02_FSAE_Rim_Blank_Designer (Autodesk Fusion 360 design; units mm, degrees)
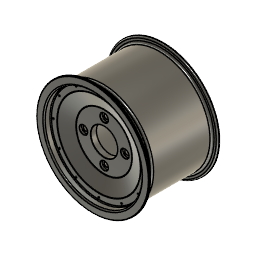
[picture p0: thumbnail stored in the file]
part number: 2026-07-27-09-56-27-671
sketch "Sketch1" plane through (0, 0, 0) normal (1, 0, 0) x axis (0, 1, 0)
  line L1 (153.5, 0) -> (0, 0)
  line L2 (0, 119.5) -> (0, 104)
  line L3 (143.5, 124.5) -> (5, 124.5)
  line L4 (148.5, 134.75) -> (148.5, 129.5)
  line L5 (153.5, 138.25) -> (152, 138.25)
  line L6 (2.5, 119.5) -> (2.5, 104)
  line L7 (143.5, 122) -> (5, 122)
  line L8 (151, 134.75) -> (151, 129.5)
  line L9 (153.5, 135.75) -> (152, 135.75)
  line L10 (2.5, 104) -> (0, 104)
  line L11 (153.5, 135.75) -> (153.5, 138.25)
  arc A1 centre (152, 134.75) radius 3.5 clockwise from (148.5, 134.75) to (152, 138.25)
  arc A2 centre (143.5, 129.5) radius 5 clockwise from (148.5, 129.5) to (143.5, 124.5)
  arc A3 centre (5, 119.5) radius 5 clockwise from (0, 119.5) to (5, 124.5)
  arc A4 centre (5, 119.5) radius 2.5 clockwise from (2.5, 119.5) to (5, 122)
  arc A5 centre (143.5, 129.5) radius 7.5 clockwise from (151, 129.5) to (143.5, 122)
  arc A6 centre (152, 134.75) radius 1 clockwise from (151, 134.75) to (152, 135.75)
  point P1 (0, 0)
  point P2 (0, 0)
  point P4 (0, 104)
  point P3 (153.5, 0)
  point P7 (153.5, 138.25)
  point P6 (148.5, 124.5)
  point P5 (0, 124.5)
  coincident P1 P2
  horizontal L1
  perpendicular L1 L2
  perpendicular L2 L3
  perpendicular L3 L4
  perpendicular L4 L5
  vertical P1 P4
  vertical P3 P7
  tangent L4 A1
  tangent L5 A1
  coincident P6 L3
  coincident P6 L4
  tangent L3 A2
  tangent L4 A2
  coincident P5 L2
  coincident P5 L3
  tangent L2 A3
  tangent L3 A3
  equal A2 A3
  perpendicular L6 L10
  perpendicular L9 L11
  dimension "d1" distance P2 P3 = 153.5
  dimension "d2" = 208
  dimension "d3" = 249
  dimension "d4" = 276.5
  dimension "d5" distance P5 P6 = 148.5
  dimension "d6" radius A1 = 3.5
  dimension "d7" radius A2 = 5
  dimension "d8" = 2.5
revolve "Revolve1" sketch "Sketch1" AlongAngle 360 bodies "FSAE Rim Back"
sketch "Sketch2" plane through (0, 0, 0) normal (0, -1, 0) x axis (1, 0, 0)
  circle C1 centre (0, 0) radius 104
  circle C2 centre (0, 0) radius 119.5
  circle C3 centre (0, 0) radius 112
  circle C4 centre (0, 112) radius 2.15
  point P1 (0, 0)
  point P3 (0, 0)
  point P4 (0, 112)
  coincident P1 P3
  coincident C3 P4
  vertical P3 P4
  dimension "d10" diameter C3 = 224
  dimension "d11" diameter C4 = 4.3
extrude "Extrude1" cut sketch "Sketch2" profile of C4 to an object
circular_pattern "C-Pattern1" TotalAngle 360
canvas "Canvas1"
move "Move1"
sketch "Sketch4" plane through (0, 0, 0) normal (1, 0, 0) x axis (0, 1, 0)
  line L1 (14, 0) -> (0, 0)
  line L2 (14, 72.5) -> (14, 0)
  line L3 (-8, 102.5) -> (14, 72.5)
  line L4 (-8, 124.5) -> (-8, 102.5)
  line L5 (-23.5, 124.5) -> (-8, 124.5)
  line L6 (-23.5, 138) -> (-23.5, 124.5)
  line L7 (-28.25, 138) -> (-23.5, 138)
  line L8 (-28.25, 0) -> (-28.25, 138)
  line L9 (0, 0) -> (-28.25, 0)
  line L10 (-13, 118.1658) -> (-28.25, 119.5)
  line L11 (-13, 102.5) -> (-13, 118.1658)
  line L12 (0, 68.6338) -> (-13, 102.5)
  line L13 (0, 0) -> (0, 68.6338)
  point P1 (0, 0)
  point P2 (0, 0)
  point P11 (0, 0)
  point P12 (-28.25, 119.5)
  point P5 (-8, 102.5)
  point P14 (-13, 102.5)
  point P3 (14, 0)
  point P4 (14, 72.5)
  point P6 (-8, 124.5)
  point P8 (-23.5, 138)
  point P9 (-28.25, 138)
  coincident P1 P2
  horizontal L1
  perpendicular L1 L2
  perpendicular L1 L4
  perpendicular L4 L5
  perpendicular L5 L6
  perpendicular L6 L7
  coincident P1 P11
  collinear L1 L9
  perpendicular L8 L9
  coincident L8 P12
  parallel L8 L11
  vertical L13
  horizontal P5 P14
  dimension "d29" distance P2 P3 = 14
  dimension "d30" = 145
  dimension "d31" = 205
  dimension "d32" = 249
  dimension "d33" = 276
  dimension "d34" distance P4 P6 = 22
  dimension "d35" distance P6 P8 = 15.5
  dimension "d36" distance P8 P9 = 4.75
  dimension "d37" distance L4 L11 = 5
  dimension "d38" angle L12 L13 = 159
  dimension "d39" angle L10 L11 = 95
  dimension "d40" = 239
revolve "Revolve3" sketch "Sketch4" AlongAngle 360 bodies "FSAE Rim Front"
sketch "Sketch5" plane through (0, 0, 0) normal (0, -1, 0) x axis (1, 0, 0)
  circle C1 centre (0, 0) radius 68.6338
  circle C2 centre (0, 0) radius 33
  point P1 (0, 0)
  point P3 (0, 0)
  coincident P1 P3
  dimension "d42" diameter C2 = 66
extrude "Extrude2" cut sketch "Sketch5" profile of C2 to an object
sketch "Sketch6" plane through (0, 0, 0) normal (0, -1, 0) x axis (1, 0, 0)
  circle C1 centre (0, 0) radius 33
  circle C2 centre (0, 0) radius 68.6338
  circle C3 centre (0, 0) radius 50.8
  point P1 (0, 0)
  point P4 (0, 0)
  point P3 (0, 50.8)
  coincident P1 P4
  coincident P3 C3
  vertical P1 P3
  dimension "d45" diameter C3 = 101.6
hole "Hole1" HoleDiameter 10.5 TipAngle 180 CBDepth 5 CBDiameter 20
chamfer "Chamfer2" sketch "Sketch1" distance 0.5
circular_pattern "C-Pattern2" TotalAngle 360
sketch "Sketch7" plane through (0, -13, 0) normal (0, -1, 0) x axis (1, 0, 0)
  circle C1 centre (0, 0) radius 102.5
  circle C2 centre (0, 0) radius 118.1658
  circle C3 centre (0, 0) radius 112
  point P1 (0, 0)
  point P3 (0, 0)
  point P4 (0, 112)
  coincident P1 P3
  coincident C3 P4
  vertical P1 P4
  dimension "d53" diameter C3 = 224
hole "Hole2" HoleDiameter 4.3 TipAngle 180
circular_pattern "C-Pattern3" TotalAngle 360
fillet "Fillet1" radius 1 3 2
chamfer "Chamfer1" distance 0.5
named bodies: "FSAE Rim Back", "FSAE Rim Front"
